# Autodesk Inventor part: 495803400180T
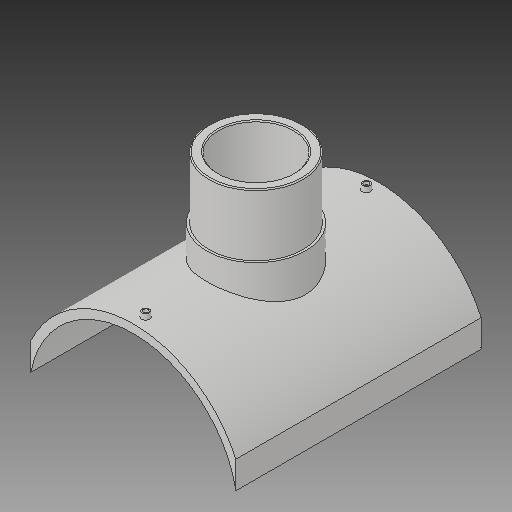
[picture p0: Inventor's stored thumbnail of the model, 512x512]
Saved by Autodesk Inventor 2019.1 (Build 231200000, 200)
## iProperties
Created: 2017-10
Part Number: 495803400180T
Material: Generic
Description: PLASSON BRANCH SADDLE  400x180
Document SubType Name: Modeling
Designer: KIM
Mass: 2754.05 g
Surface Area: 3037.44 cm^2
Volume: 2754.05 cm^3
Density: 1 g/cm^3
Appearance: Default
Author: KIM
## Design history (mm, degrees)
derived "495803.ipt"
feature "Solid1::495803.ipt"
tag "TaggingFeature1"
body "Solid1"
other parameters: "d1" = 16, "d2" = 393, "d4" = 0, "d12" = 225.6, "d13" = 14, "d14" = 211.5, "d16" = 5 deg, "d18" = 4, "d19" = 14, "d20" = 0, "d21" = 3, "d22" = 0, "d23" = 385, "d24" = 189, "d25" = 16, "d26" = 144, "d28" = 0, "d29" = 9.6, "d31" = 0, "d32" = 84.5, "d33" = 0, "d34" = 4, "d37" = 118.3, "d38" = 0, "d39" = 2, "B_" = 393, "H_" = 169, "x_" = 16, "D_" = 16
